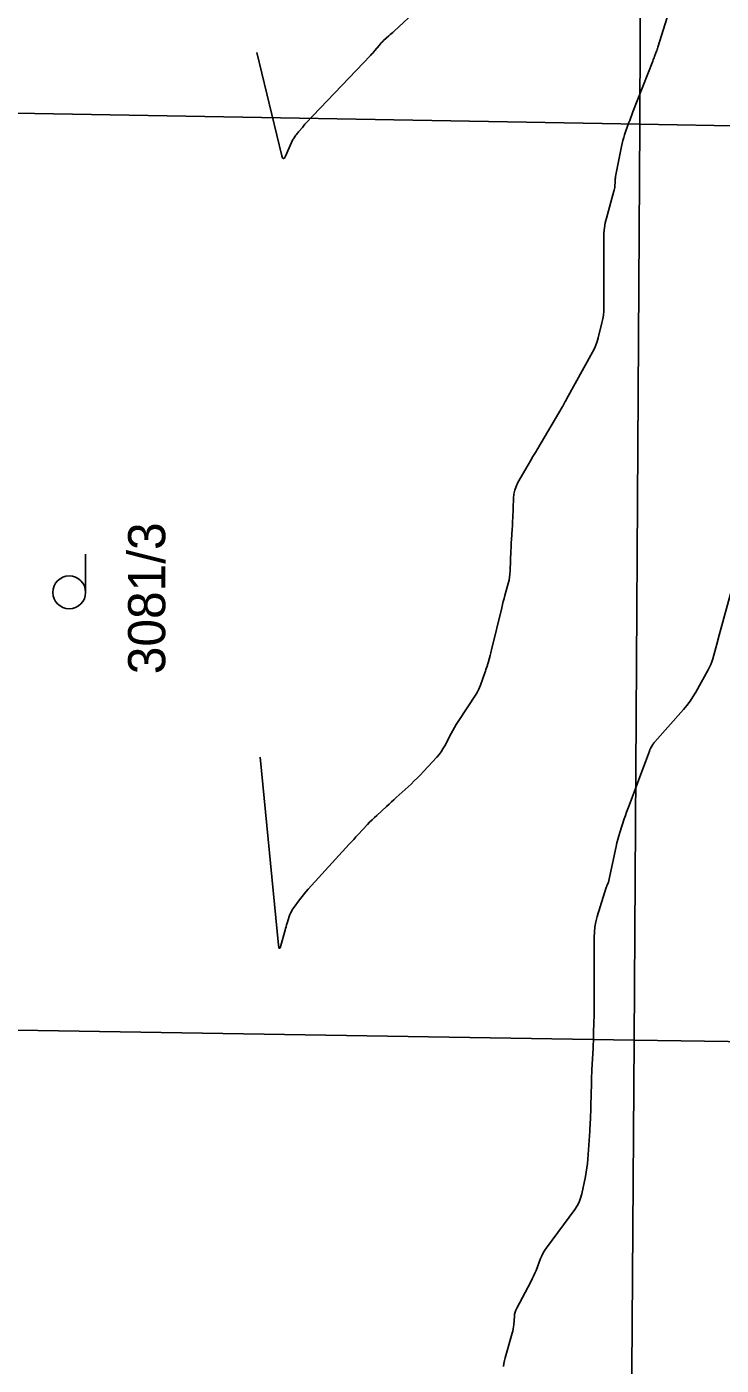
# Model space of a CAD drawing. Extents: x -534410 to -534262, y -1190162 to -1189584.
# Drawn here: x -534356.09 to -534340.2, y -1190052.88 to -1190022.24 of the extents above; entities that cross this region are included whole.
import ezdxf

# ---------------------------------------------------------------- set-up
doc = ezdxf.new("R2010")
doc.units = 0
for name, color, linetype in [('30', 7, 'Continuous'), ('31', 7, 'Continuous'), ('Hranice parcel', 7, 'Continuous'), ('Parcelní čísla', 7, 'Continuous'), ('Značky kultur', 7, 'Continuous')]:
    doc.layers.add(name, color=color, linetype=linetype)

msp = doc.modelspace()

# ---------------------------------------------------------------- linework, layer by layer
at = {"layer": '30'}
msp.add_lwpolyline([(-534341.265, -1190021.485), (-534341.645, -1190022.709), (-534341.654, -1190022.736), (-534341.663, -1190022.763), (-534341.673, -1190022.79), (-534341.682, -1190022.817), (-534341.723, -1190022.922), (-534341.733, -1190022.949), (-534341.743, -1190022.975), (-534341.753, -1190023.002), (-534341.764, -1190023.028), (-534342.218, -1190024.189), (-534342.243, -1190024.254), (-534342.268, -1190024.319), (-534342.292, -1190024.385), (-534342.315, -1190024.45), (-534342.407, -1190024.713), (-534342.429, -1190024.779), (-534342.448, -1190024.846), (-534342.465, -1190024.913), (-534342.479, -1190024.981), (-534342.613, -1190025.67), (-534342.618, -1190025.698), (-534342.622, -1190025.726), (-534342.625, -1190025.754), (-534342.627, -1190025.782), (-534342.633, -1190025.895), (-534342.635, -1190025.923), (-534342.639, -1190025.951), (-534342.644, -1190025.979), (-534342.651, -1190026.006), (-534342.822, -1190026.621), (-534342.849, -1190026.733), (-534342.868, -1190026.847), (-534342.88, -1190026.961), (-534342.884, -1190027.076), (-534342.884, -1190028.667), (-534342.886, -1190028.756), (-534342.894, -1190028.843), (-534342.908, -1190028.93), (-534342.927, -1190029.017), (-534343.012, -1190029.361), (-534343.036, -1190029.446), (-534343.065, -1190029.529), (-534343.1, -1190029.609), (-534343.141, -1190029.688), (-534343.737, -1190030.764), (-534343.743, -1190030.776), (-534343.749, -1190030.787), (-534343.76, -1190030.81), (-534343.766, -1190030.822), (-534343.772, -1190030.833), (-534343.808, -1190030.898), (-534343.815, -1190030.911), (-534343.822, -1190030.924), (-534343.83, -1190030.936), (-534343.837, -1190030.949), (-534344.393, -1190031.893), (-534344.449, -1190031.988), (-534344.505, -1190032.083), (-534344.56, -1190032.178), (-534344.615, -1190032.273), (-534344.849, -1190032.677), (-534344.891, -1190032.763), (-534344.923, -1190032.851), (-534344.943, -1190032.943), (-534344.952, -1190033.037), (-534344.967, -1190033.493), (-534344.97, -1190033.555), (-534344.972, -1190033.616), (-534344.976, -1190033.678), (-534344.98, -1190033.739), (-534344.997, -1190033.984), (-534345.001, -1190034.045), (-534345.004, -1190034.107), (-534345.007, -1190034.168), (-534345.01, -1190034.23), (-534345.027, -1190034.7), (-534345.031, -1190034.772), (-534345.04, -1190034.843), (-534345.053, -1190034.914), (-534345.071, -1190034.984), (-534345.148, -1190035.262), (-534345.167, -1190035.332), (-534345.185, -1190035.401), (-534345.203, -1190035.471), (-534345.22, -1190035.541), (-534345.453, -1190036.502), (-534345.461, -1190036.537), (-534345.47, -1190036.571), (-534345.479, -1190036.605), (-534345.488, -1190036.639), (-534345.531, -1190036.806), (-534345.537, -1190036.825), (-534345.542, -1190036.844), (-534345.548, -1190036.863), (-534345.555, -1190036.882), (-534345.581, -1190036.956), (-534345.594, -1190036.993), (-534345.607, -1190037.03), (-534345.706, -1190037.315), (-534345.726, -1190037.368), (-534345.749, -1190037.42), (-534345.776, -1190037.47), (-534345.805, -1190037.518), (-534346.218, -1190038.15), (-534346.261, -1190038.217), (-534346.301, -1190038.285), (-534346.341, -1190038.354), (-534346.378, -1190038.423), (-534346.525, -1190038.704), (-534346.564, -1190038.773), (-534346.607, -1190038.839), (-534346.654, -1190038.901), (-534346.706, -1190038.961), (-534347.01, -1190039.292), (-534347.079, -1190039.365), (-534347.15, -1190039.438), (-534347.222, -1190039.508), (-534347.296, -1190039.578), (-534347.632, -1190039.887), (-534347.687, -1190039.938), (-534347.743, -1190039.989), (-534347.799, -1190040.04), (-534347.855, -1190040.091), (-534348.079, -1190040.295), (-534348.134, -1190040.347), (-534348.188, -1190040.399), (-534348.242, -1190040.453), (-534348.294, -1190040.508), (-534348.503, -1190040.733), (-534348.555, -1190040.789), (-534348.606, -1190040.845), (-534348.658, -1190040.901), (-534348.71, -1190040.957), (-534349.651, -1190041.986), (-534349.696, -1190042.036), (-534349.74, -1190042.088), (-534349.782, -1190042.142), (-534349.822, -1190042.196), (-534350.012, -1190042.461), (-534350.034, -1190042.495), (-534350.054, -1190042.531), (-534350.07, -1190042.568), (-534350.083, -1190042.607), (-534350.131, -1190042.765), (-534350.142, -1190042.805), (-534350.154, -1190042.845), (-534350.165, -1190042.884), (-534350.177, -1190042.924), (-534350.274, -1190043.273), (-534350.292, -1190043.326), (-534350.307, -1190043.343), (-534350.319, -1190043.323), (-534350.328, -1190043.268), (-534350.749, -1190038.959)], dxfattribs=at)
at = {"layer": '31'}
for points in [[(-534347.138, -1190021.837), (-534347.685, -1190022.342), (-534347.714, -1190022.369), (-534347.743, -1190022.396), (-534347.772, -1190022.422), (-534347.802, -1190022.449), (-534347.922, -1190022.559), (-534347.949, -1190022.585), (-534347.976, -1190022.612), (-534348.001, -1190022.64), (-534348.026, -1190022.669), (-534348.122, -1190022.786), (-534348.146, -1190022.815), (-534348.171, -1190022.844), (-534348.197, -1190022.872), (-534348.223, -1190022.899), (-534349.701, -1190024.452), (-534349.722, -1190024.474), (-534349.742, -1190024.497), (-534349.763, -1190024.521), (-534349.782, -1190024.544), (-534349.87, -1190024.65), (-534349.885, -1190024.669), (-534349.9, -1190024.688), (-534349.914, -1190024.707), (-534349.928, -1190024.726), (-534349.984, -1190024.805), (-534349.997, -1190024.825), (-534350.009, -1190024.846), (-534350.02, -1190024.867), (-534350.031, -1190024.889), (-534350.169, -1190025.203), (-534350.194, -1190025.247), (-534350.216, -1190025.261), (-534350.235, -1190025.244), (-534350.252, -1190025.196), (-534350.824, -1190022.831)], [(-534339.949, -1190035.085), (-534340.244, -1190036.173), (-534340.299, -1190036.374), (-534340.39, -1190036.71), (-534340.41, -1190036.777), (-534340.434, -1190036.841), (-534340.462, -1190036.904), (-534340.494, -1190036.966), (-534340.781, -1190037.477), (-534340.843, -1190037.581), (-534340.91, -1190037.68), (-534340.982, -1190037.777), (-534341.06, -1190037.869), (-534341.719, -1190038.614), (-534341.731, -1190038.628), (-534341.742, -1190038.643), (-534341.752, -1190038.658), (-534341.762, -1190038.673), (-534341.809, -1190038.75), (-534341.814, -1190038.759), (-534341.819, -1190038.768), (-534341.823, -1190038.777), (-534341.827, -1190038.787), (-534341.842, -1190038.825), (-534341.849, -1190038.845), (-534341.856, -1190038.864), (-534341.893, -1190038.968), (-534341.901, -1190038.989), (-534341.908, -1190039.009), (-534341.916, -1190039.03), (-534341.923, -1190039.05), (-534342.307, -1190040.07), (-534342.335, -1190040.146), (-534342.363, -1190040.223), (-534342.39, -1190040.301), (-534342.416, -1190040.378), (-534342.519, -1190040.689), (-534342.543, -1190040.767), (-534342.566, -1190040.846), (-534342.586, -1190040.925), (-534342.604, -1190041.005), (-534342.766, -1190041.788), (-534342.769, -1190041.802), (-534342.773, -1190041.815), (-534342.778, -1190041.829), (-534342.784, -1190041.842), (-534342.807, -1190041.894), (-534342.812, -1190041.907), (-534342.818, -1190041.92), (-534342.823, -1190041.934), (-534342.827, -1190041.947), (-534343.033, -1190042.613), (-534343.065, -1190042.73), (-534343.087, -1190042.847), (-534343.1, -1190042.966), (-534343.105, -1190043.086), (-534343.105, -1190044.689), (-534343.105, -1190044.767), (-534343.106, -1190044.844), (-534343.107, -1190044.922), (-534343.109, -1190045), (-534343.117, -1190045.311), (-534343.119, -1190045.389), (-534343.122, -1190045.467), (-534343.125, -1190045.544), (-534343.129, -1190045.622), (-534343.155, -1190046.119), (-534343.158, -1190046.191), (-534343.162, -1190046.264), (-534343.164, -1190046.336), (-534343.166, -1190046.409), (-534343.174, -1190046.708), (-534343.176, -1190046.776), (-534343.178, -1190046.844), (-534343.18, -1190046.913), (-534343.183, -1190046.981), (-534343.192, -1190047.255), (-534343.194, -1190047.323), (-534343.198, -1190047.391), (-534343.201, -1190047.459), (-534343.206, -1190047.528), (-534343.25, -1190048.164), (-534343.259, -1190048.265), (-534343.271, -1190048.365), (-534343.287, -1190048.464), (-534343.306, -1190048.564), (-534343.388, -1190048.96), (-534343.414, -1190049.057), (-534343.449, -1190049.149), (-534343.495, -1190049.237), (-534343.55, -1190049.321), (-534344.193, -1190050.193), (-534344.234, -1190050.252), (-534344.27, -1190050.313), (-534344.303, -1190050.377), (-534344.331, -1190050.443), (-534344.434, -1190050.711), (-534344.461, -1190050.777), (-534344.49, -1190050.843), (-534344.521, -1190050.907), (-534344.554, -1190050.971), (-534344.878, -1190051.577), (-534344.899, -1190051.621), (-534344.914, -1190051.666), (-534344.925, -1190051.713), (-534344.931, -1190051.761), (-534344.945, -1190051.956), (-534344.949, -1190052.004), (-534344.957, -1190052.052), (-534344.966, -1190052.1), (-534344.978, -1190052.147), (-534345.141, -1190052.713), (-534345.157, -1190052.779), (-534345.17, -1190052.846), (-534345.178, -1190052.913)]]:
    msp.add_lwpolyline(points, dxfattribs=at)
at = {"layer": 'Hranice parcel'}
for p, q in [((-534366.35, -1190024.04), (-534342.06, -1190024.47)), ((-534342.19, -1190045.44), (-534342.06, -1190024.47)), ((-534342.06, -1190024.47), (-534333.46, -1190024.63)), ((-534366.87, -1190045.04), (-534342.19, -1190045.44)), ((-534342.19, -1190045.44), (-534334.16, -1190045.57))]:
    msp.add_line(p, q, dxfattribs=at)
for points in [[(-534342.06, -1190024.47), (-534342.05, -1190022.37), (-534341.99, -1190003.45)], [(-534342.35, -1190068.22), (-534342.22, -1190049.76), (-534342.19, -1190045.44)]]:
    msp.add_lwpolyline(points, dxfattribs=at)
at = {"layer": 'Značky kultur'}
msp.add_line((-534354.742, -1190035.19), (-534354.742, -1190034.315), dxfattribs=at)
msp.add_circle((-534355.117, -1190035.19), 0.375, dxfattribs=at)

# ---------------------------------------------------------------- texts
at = {"layer": 'Parcelní čísla'}
msp.add_text('3081/3', height=0.85, rotation=90, dxfattribs=at).set_placement((-534352.92, -1190037.064))

doc.saveas('drawing.dxf')
